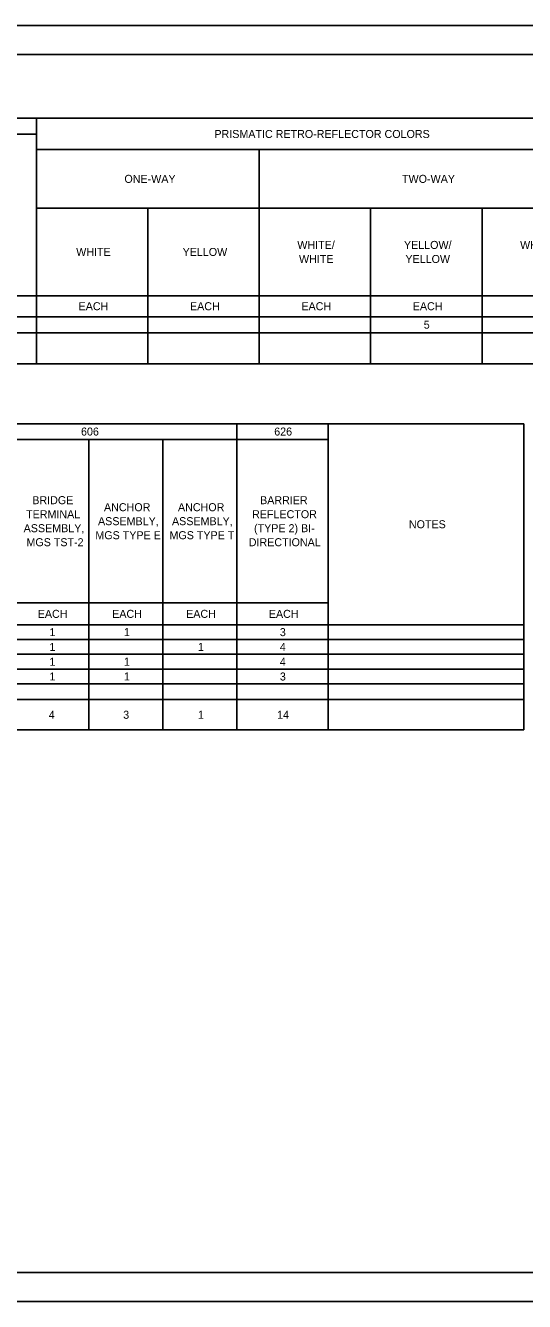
# Model space of a CAD drawing. Extents: x 0 to 34, y 0 to 22.
# Drawn here: x 13.79 to 22.39, y 0 to 22 of the extents above; entities that cross this region are included whole.
import ezdxf

# ---------------------------------------------------------------- set-up
doc = ezdxf.new("R2010")
doc.units = 0
for name, color, linetype in [('SH_Border', 7, 'Continuous'), ('SH_Cut_Line', 7, 'Continuous'), ('SH_Text', 7, 'Continuous')]:
    doc.layers.add(name, color=color, linetype=linetype)

msp = doc.modelspace()

# ---------------------------------------------------------------- linework, layer by layer
at = {"layer": 'SH_Border'}
msp.add_lwpolyline([(1.5, 21.5), (33.5, 21.5), (33.5, 0.5), (1.5, 0.5)], close=True, dxfattribs=at)
at = {"layer": 'SH_Cut_Line'}
msp.add_lwpolyline([(0, 0), (34, 0), (34, 22), (0, 22)], close=True, dxfattribs=at)
at = {"layer": 'SH_Text'}
for p, q in [((9.178, 20.4), (23.578, 20.4)), ((13.978, 20.4), (13.978, 18.852)), ((12.058, 20.124), (13.978, 20.124)), ((13.978, 19.86), (23.578, 19.86)), ((17.818, 19.86), (17.818, 18.852)), ((13.978, 18.852), (23.578, 18.852)), ((13.978, 18.852), (13.978, 16.164)), ((15.898, 18.852), (15.898, 16.164)), ((17.818, 18.852), (17.818, 16.164)), ((19.738, 18.852), (19.738, 16.164)), ((21.658, 18.852), (21.658, 16.164)), ((12.058, 17.34), (23.578, 17.34)), ((9.178, 16.98), (23.578, 16.98)), ((9.178, 16.704), (23.578, 16.704)), ((9.178, 16.164), (23.578, 16.164)), ((2.549, 15.134), (22.379, 15.134)), ((17.429, 15.134), (17.429, 9.854)), ((19.004, 15.134), (19.004, 9.854)), ((22.379, 15.134), (22.379, 9.854)), ((8.699, 14.864), (19.004, 14.864)), ((14.879, 14.864), (14.879, 9.854)), ((16.154, 14.864), (16.154, 9.854)), ((8.699, 12.044), (19.004, 12.044)), ((2.549, 11.669), (22.379, 11.669)), ((2.549, 11.414), (22.379, 11.414)), ((2.549, 11.159), (22.379, 11.159)), ((2.549, 10.904), (22.379, 10.904)), ((2.549, 10.649), (22.379, 10.649)), ((2.549, 10.379), (22.379, 10.379)), ((2.549, 9.854), (22.379, 9.854))]:
    msp.add_line(p, q, dxfattribs=at)

# ---------------------------------------------------------------- texts
for s, p in [('PRISMATIC RETRO-REFLECTOR COLORS', (17.045, 20.061)), ('ONE-WAY', (15.494, 19.287)), ('TWO-WAY', (20.279, 19.287)), ('WHITE/', (18.474, 18.148)), ('YELLOW/', (20.312, 18.148)), ('WHITE/', (22.314, 18.148)), ('WHITE', (14.663, 18.027)), ('YELLOW', (16.497, 18.027)), ('WHITE', (18.503, 17.906)), ('YELLOW', (20.337, 17.906)), ('EACH', (14.704, 17.091)), ('EACH', (16.624, 17.091)), ('EACH', (18.544, 17.091)), ('EACH', (20.464, 17.091)), ('5', (20.653, 16.773)), ('606', (14.746, 14.93)), ('626', (18.076, 14.93)), ('BRIDGE ', (13.906, 13.747)), ('BARRIER ', (17.832, 13.747)), ('TERMINAL ', (13.799, 13.505)), ('ANCHOR ', (15.142, 13.626)), ('ANCHOR ', (16.417, 13.626)), ('REFLECTOR', (17.694, 13.505)), ('ASSEMBLY, ', (15.039, 13.385)), ('ASSEMBLY, ', (16.314, 13.385)), ('NOTES', (20.397, 13.332)), ('ASSEMBLY,', (13.757, 13.264)), ('MGS TYPE E', (14.993, 13.143)), ('MGS TYPE T', (16.271, 13.143)), ('(TYPE 2) BI-', (17.728, 13.264)), (' MGS TST-2', (13.754, 13.022)), ('DIRECTIONAL', (17.637, 13.022)), ('EACH', (14, 11.787)), ('EACH', (15.283, 11.787)), ('EACH', (16.558, 11.787)), ('EACH', (17.983, 11.787)), ('1', (14.202, 11.472)), ('1', (15.485, 11.472)), ('3', (18.173, 11.472)), ('1', (14.202, 11.217)), ('1', (16.76, 11.217)), ('4', (18.173, 11.217)), ('1', (14.202, 10.962)), ('1', (15.485, 10.962)), ('4', (18.173, 10.962)), ('1', (14.202, 10.707)), ('1', (15.485, 10.707)), ('3', (18.173, 10.707)), ('4', (14.19, 10.047)), ('3', (15.473, 10.047)), ('1', (16.76, 10.047)), ('14', (18.125, 10.047))]:
    msp.add_text(s, height=0.138, dxfattribs=at).set_placement(p)

doc.saveas('drawing.dxf')
